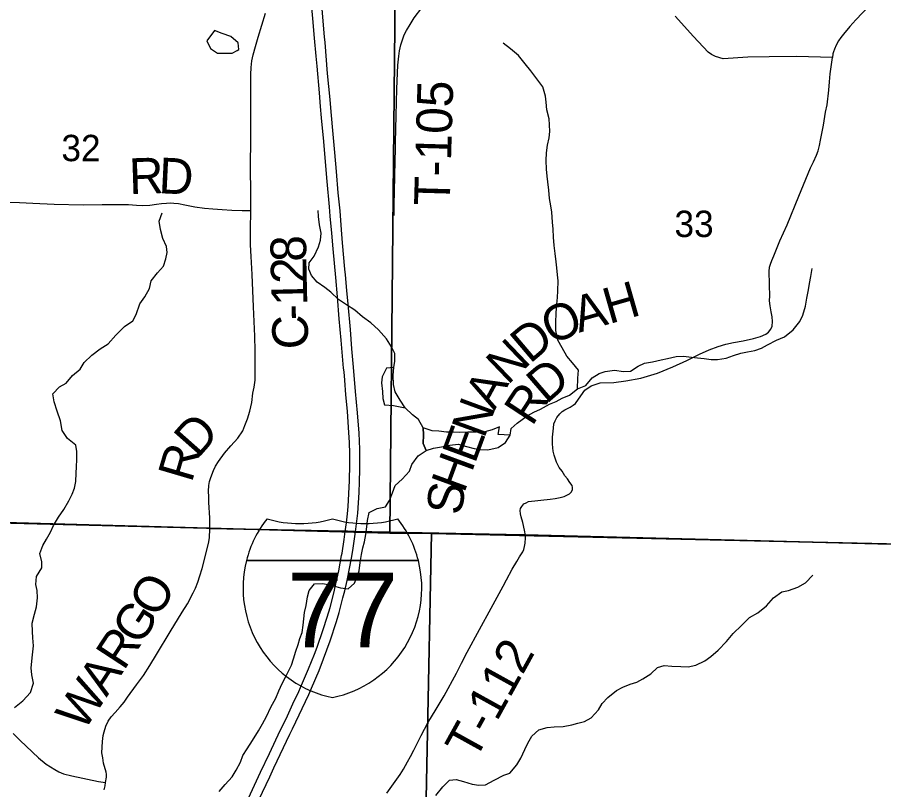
# Model space of a CAD drawing. Extents: x 0 to 34, y 0 to 22.
# Drawn here: x 6.166 to 7.543, y 15.63 to 16.857 of the extents above; entities that cross this region are included whole.
import ezdxf

# ---------------------------------------------------------------- set-up
doc = ezdxf.new("R2010")
doc.units = 0
for name, color, linetype in [('GM_X_Corporation', 7, 'Continuous'), ('GM_X_County_Road', 7, 'Continuous'), ('GM_X_County_Road_Text', 7, 'Continuous'), ('GM_X_Interstate_Location', 7, 'Continuous'), ('GM_X_Interstate_Route', 7, 'Continuous'), ('GM_X_Interstate_Shield', 7, 'Continuous'), ('GM_X_Minor_Lake', 7, 'Continuous'), ('GM_X_Minor_River', 7, 'Continuous'), ('GM_X_Section_Text', 7, 'Continuous'), ('GM_X_Township_Road', 7, 'Continuous'), ('GM_X_Township_Road_Text', 7, 'Continuous')]:
    doc.layers.add(name, color=color, linetype=linetype)

msp = doc.modelspace()

# ---------------------------------------------------------------- linework, layer by layer
at = {"layer": 'GM_X_Corporation'}
for points in [[(4.7905, 18.3604), (4.7823, 18.128), (4.7806, 18.0273), (4.765, 16.8754), (4.756, 16.2274), (4.759, 16.0879), (4.9206, 16.0842), (4.928, 16.0841), (4.9731, 16.0831), (4.975, 16.083), (5.0347, 16.0817), (5.0373, 16.0816), (6.4668, 16.045), (6.4721, 16.0449), (6.6873, 16.0404), (6.6909, 16.0403), (6.7034, 16.04), (6.9699, 16.0345), (6.9736, 16.0344), (7.8043, 16.0135), (7.8077, 16.0135), (8.4311, 16.0029), (8.4311, 20.028)], [(3.7221, 14.5734), (8.4311, 14.5734), (8.4311, 16.0029), (7.8077, 16.0135), (7.8043, 16.0135), (6.9736, 16.0344), (6.9699, 16.0345), (6.7034, 16.04), (6.6909, 16.0403), (6.6873, 16.0404), (6.4721, 16.0449), (6.4668, 16.045), (5.0373, 16.0816)]]:
    msp.add_lwpolyline(points, dxfattribs=at)
for points in [[(6.7684, 17.0582), (6.7585, 16.0372), (5.82, 16.0635), (5.7783, 16.0638), (5.7733, 17.0918)], [(7.7982, 17.0659), (7.8046, 16.0144), (6.8244, 16.0368), (6.7585, 16.0372), (6.7684, 17.0582)], [(5.82, 16.0635), (6.7585, 16.0372), (6.8244, 16.0368), (6.804, 15.0104), (5.7937, 15.0184)], [(6.8244, 16.0368), (7.8046, 16.0144), (7.7958, 14.9961), (6.804, 15.0104)]]:
    msp.add_lwpolyline(points, close=True, dxfattribs=at)
at = {"layer": 'GM_X_County_Road'}
for points in [[(7.5207, 16.8756), (7.4991, 16.8527), (7.4896, 16.8425), (7.4794, 16.8303), (7.4751, 16.8247), (7.4715, 16.8193), (7.468, 16.8128), (7.4653, 16.8065), (7.4636, 16.8022), (7.4626, 16.7986), (7.462, 16.7929), (7.4046, 16.7944), (7.3612, 16.7942), (7.3274, 16.7935), (7.2881, 16.7911), (7.2762, 16.7945), (7.2697, 16.7976), (7.2646, 16.8015), (7.2412, 16.8262), (7.2117, 16.8589)], [(6.4723, 16.0472), (6.4723, 16.0618), (6.4708, 16.0862), (6.4704, 16.0949), (6.47, 16.1041), (6.4704, 16.1128), (6.4716, 16.1192), (6.4737, 16.1259), (6.4778, 16.1367), (6.4813, 16.1438), (6.486, 16.1514), (6.4954, 16.1645), (6.5056, 16.176), (6.5169, 16.1884), (6.5244, 16.2001), (6.5279, 16.2085), (6.532, 16.2189), (6.5359, 16.2313), (6.5388, 16.245), (6.5407, 16.2595), (6.5426, 16.269), (6.544, 16.2805), (6.5443, 16.2919), (6.5444, 16.3002), (6.5442, 16.3116), (6.544, 16.3268), (6.5435, 16.3502), (6.5413, 16.3968), (6.5394, 16.448), (6.5377, 16.4771), (6.5369, 16.4954), (6.5368, 16.519), (6.5375, 16.55), (6.5375, 16.5775), (6.5366, 16.6182), (6.5368, 16.6318), (6.5373, 16.6517), (6.5374, 16.683), (6.5375, 16.7112), (6.5374, 16.7438), (6.5374, 16.7581), (6.5374, 16.7661), (6.5376, 16.7771), (6.5391, 16.7879), (6.541, 16.7973), (6.5448, 16.8104), (6.5491, 16.8253), (6.5606, 16.8635)], [(6.3042, 15.6295), (6.3057, 15.6357), (6.3064, 15.641), (6.3079, 15.6496), (6.3077, 15.6542), (6.3071, 15.6578), (6.3032, 15.6719), (6.3018, 15.6801), (6.3007, 15.6884), (6.3016, 15.7065), (6.3026, 15.7158), (6.304, 15.7218), (6.307, 15.7308), (6.3103, 15.7384), (6.3154, 15.7455), (6.3214, 15.7525), (6.3298, 15.7616), (6.3358, 15.7687), (6.3413, 15.7767), (6.3555, 15.7964), (6.3668, 15.8109), (6.377, 15.8272), (6.3872, 15.8444), (6.4091, 15.8806), (6.4284, 15.9117), (6.4365, 15.9252), (6.4457, 15.9424), (6.4491, 15.9501), (6.453, 15.9595), (6.4565, 15.9693), (6.4599, 15.9811), (6.47, 16.0207), (6.4715, 16.0298), (6.4723, 16.0443), (6.4723, 16.0472)], [(6.1595, 15.7191), (6.1705, 15.7081), (6.1803, 15.6988), (6.1998, 15.6805), (6.212, 15.6705), (6.2256, 15.6618), (6.2321, 15.6582), (6.2395, 15.655), (6.2527, 15.6517), (6.2951, 15.6427), (6.3064, 15.641)]]:
    msp.add_lwpolyline(points, dxfattribs=at)
at = {"layer": 'GM_X_Interstate_Route'}
for points in [[(6.5303, 15.6094), (6.5528, 15.6576), (6.567, 15.6873), (6.5841, 15.7238), (6.5934, 15.7425), (6.6043, 15.7661), (6.6135, 15.7857), (6.6165, 15.7923), (6.6291, 15.8215), (6.6384, 15.8449), (6.6429, 15.8564), (6.6525, 15.8844), (6.6587, 15.904), (6.6632, 15.9191), (6.6701, 15.9463), (6.6709, 15.9499), (6.6772, 15.9777), (6.6817, 16.0019), (6.6824, 16.0056), (6.6858, 16.0273), (6.6875, 16.0398), (6.6893, 16.0536), (6.6908, 16.0678), (6.6919, 16.0798), (6.6944, 16.1205), (6.6947, 16.1462), (6.6945, 16.1641), (6.6941, 16.1816), (6.6928, 16.205), (6.6909, 16.2313), (6.6885, 16.2572), (6.6865, 16.2803), (6.6855, 16.2935), (6.6849, 16.2996), (6.6809, 16.3438), (6.6796, 16.3609), (6.678, 16.3779), (6.6749, 16.4126), (6.6723, 16.4434), (6.6682, 16.4891), (6.6661, 16.5138), (6.6636, 16.5409), (6.6623, 16.556), (6.6588, 16.5958), (6.6561, 16.6272), (6.6533, 16.6598), (6.6497, 16.6974), (6.6481, 16.7151), (6.6463, 16.737), (6.6426, 16.7794), (6.6414, 16.7949), (6.6387, 16.8239), (6.6359, 16.8552), (6.634, 16.8779)], [(6.5385, 15.5891), (6.5676, 15.6502), (6.574, 15.6644), (6.5995, 15.7179), (6.6035, 15.7263), (6.6294, 15.7811), (6.634, 15.7912), (6.6458, 15.8193), (6.6531, 15.8376), (6.6636, 15.8661), (6.6734, 15.897), (6.6775, 15.9115), (6.6838, 15.9344), (6.6865, 15.9459), (6.6902, 15.9623), (6.6942, 15.9813), (6.6972, 15.9974), (6.6994, 16.0099), (6.7036, 16.0395), (6.7072, 16.0691), (6.7094, 16.1018), (6.71, 16.1186), (6.7106, 16.1386), (6.7105, 16.171), (6.7095, 16.196), (6.7071, 16.2285), (6.7039, 16.2626), (6.7006, 16.3012), (6.6981, 16.3303), (6.6956, 16.3607), (6.6918, 16.4012), (6.69, 16.4229), (6.6878, 16.4476), (6.6869, 16.4569), (6.6833, 16.4987), (6.6814, 16.5193), (6.6791, 16.5494), (6.6764, 16.578), (6.6734, 16.6121), (6.6707, 16.6422), (6.6671, 16.6827), (6.6644, 16.7133), (6.6632, 16.7261), (6.6594, 16.7677), (6.6553, 16.8166), (6.6544, 16.826), (6.6501, 16.8761)]]:
    msp.add_lwpolyline(points, dxfattribs=at)
at = {"layer": 'GM_X_Interstate_Shield'}
for p, q in [((6.5304, 15.9937), (6.8036, 15.9937)), ((6.8036, 15.9937), (6.5304, 15.9937)), ((6.8036, 15.9937), (6.5304, 15.9937))]:
    msp.add_line(p, q, dxfattribs=at)
for centre, start, end in [((6.7025, 15.9501), 141.669, 165.8066), ((6.6151, 16.2301), 253.0091, 286.9909), ((6.7189, 16.2301), 253.0091, 286.9909), ((6.6315, 15.9501), 14.1934, 38.331), ((6.7025, 15.9501), 165.8066, 258.463), ((6.6315, 15.9501), 281.537, 14.1934)]:
    msp.add_arc(centre, 0.1776, start, end, dxfattribs=at)
at = {"layer": 'GM_X_Minor_Lake'}
for points in [[(6.4793, 16.8357), (6.4673, 16.8197), (6.4734, 16.8072), (6.4844, 16.8), (6.5075, 16.8001), (6.5156, 16.8044)], [(6.5156, 16.8044), (6.5184, 16.8058), (6.5172, 16.8165), (6.5055, 16.8263), (6.4918, 16.8311), (6.4793, 16.8357)], [(6.7645, 16.3006), (6.7532, 16.2994), (6.746, 16.2858), (6.7449, 16.2763), (6.7464, 16.2623), (6.7472, 16.2513), (6.7499, 16.2411), (6.7639, 16.2403), (6.7829, 16.2366)], [(6.7829, 16.2366), (6.7745, 16.2487), (6.7669, 16.262), (6.7642, 16.2733), (6.7634, 16.2885), (6.7645, 16.3006)], [(6.8114, 16.2045), (6.8118, 16.1935), (6.8111, 16.1799), (6.816, 16.1685), (6.8277, 16.1723), (6.8406, 16.1747), (6.8539, 16.177), (6.8667, 16.1785), (6.88, 16.1752), (6.8921, 16.1718), (6.9016, 16.1703), (6.9141, 16.1696), (6.9307, 16.1735), (6.9421, 16.1811), (6.9496, 16.1932)], [(6.9496, 16.1932), (6.9307, 16.1939), (6.9329, 16.2061), (6.9208, 16.2015), (6.9091, 16.1984), (6.8958, 16.198), (6.8822, 16.1979), (6.8697, 16.1971), (6.8595, 16.1978), (6.8485, 16.1978), (6.8364, 16.1993), (6.8254, 16.2), (6.8114, 16.2045)]]:
    msp.add_lwpolyline(points, dxfattribs=at)
at = {"layer": 'GM_X_Minor_River'}
for points in [[(7.0565, 16.2668), (7.0572, 16.2838), (7.058, 16.296), (7.0485, 16.3081), (7.0397, 16.3186), (7.0321, 16.3319), (7.0256, 16.344), (7.0222, 16.3595), (7.0221, 16.3713), (7.0229, 16.3876), (7.0236, 16.4009), (7.0247, 16.4119), (7.0254, 16.4225), (7.0257, 16.438), (7.0249, 16.4479), (7.0238, 16.4589), (7.0226, 16.4683), (7.0211, 16.4816), (7.0195, 16.4941), (7.0183, 16.5074), (7.0179, 16.5202), (7.0167, 16.5312), (7.0156, 16.5475), (7.014, 16.5574), (7.0121, 16.5691), (7.0109, 16.582), (7.0097, 16.5953), (7.0086, 16.6047), (7.0074, 16.6154), (7.0066, 16.6294), (7.0073, 16.6415), (7.0092, 16.654), (7.0114, 16.6654), (7.0125, 16.6753), (7.0121, 16.6863), (7.0117, 16.6957), (7.0079, 16.7101), (7.0067, 16.7223), (7.0059, 16.7317), (7.0017, 16.7465), (6.9918, 16.759), (6.9827, 16.7718), (6.9736, 16.7832), (6.963, 16.796), (6.95, 16.8066), (6.9383, 16.816)], [(6.1618, 15.7601), (6.1747, 15.7708), (6.1871, 15.7841), (6.192, 15.7989), (6.1889, 15.8122), (6.1882, 15.8236), (6.1904, 15.844), (6.1918, 15.8581), (6.1907, 15.871), (6.1903, 15.8812), (6.1898, 15.8945), (6.1932, 15.9085), (6.1966, 15.9203), (6.198, 15.9343), (6.1976, 15.946), (6.1953, 15.9555), (6.1968, 15.9684), (6.2051, 15.9821), (6.2051, 15.9916), (6.202, 16.0052), (6.2069, 16.0177), (6.2125, 16.0276), (6.2189, 16.039), (6.2234, 16.0493), (6.2317, 16.0626), (6.24, 16.0751), (6.2479, 16.0884), (6.2532, 16.0994), (6.257, 16.1089), (6.2592, 16.1195), (6.2599, 16.1324), (6.2603, 16.1427), (6.2606, 16.1544), (6.2606, 16.1673), (6.259, 16.1771), (6.2457, 16.1877), (6.2374, 16.2006), (6.2347, 16.2157), (6.2297, 16.2313), (6.2248, 16.246), (6.2224, 16.2589), (6.2334, 16.2696), (6.244, 16.2757), (6.2538, 16.2878), (6.2659, 16.2977), (6.2723, 16.3084), (6.2844, 16.3202), (6.2976, 16.3301), (6.3104, 16.3381), (6.3225, 16.3521), (6.3365, 16.3655), (6.3497, 16.3746), (6.355, 16.3849), (6.361, 16.4016), (6.3689, 16.413), (6.3764, 16.4259), (6.379, 16.4384), (6.3892, 16.4509), (6.3983, 16.4616), (6.402, 16.473), (6.4043, 16.4832), (6.4035, 16.4927), (6.3974, 16.5052), (6.3939, 16.5196), (6.3916, 16.5332), (6.3965, 16.5461)], [(6.816, 16.1685), (6.8111, 16.1799), (6.8118, 16.1935), (6.8114, 16.2045), (6.8038, 16.2181), (6.7943, 16.2253), (6.7829, 16.2366), (6.7745, 16.2487), (6.7669, 16.262), (6.7642, 16.2733), (6.7634, 16.2885), (6.7645, 16.3006), (6.7664, 16.3105), (6.766, 16.323), (6.761, 16.3332), (6.753, 16.3461), (6.7405, 16.3601), (6.728, 16.3714), (6.715, 16.3808), (6.7029, 16.3914), (6.6892, 16.4001), (6.6767, 16.4087), (6.6646, 16.4201), (6.6547, 16.4276), (6.6426, 16.4359), (6.6338, 16.4465), (6.6296, 16.4567), (6.63, 16.4666), (6.6379, 16.4776), (6.6451, 16.492), (6.648, 16.5027), (6.6491, 16.514), (6.6465, 16.5273), (6.6449, 16.5402), (6.6445, 16.55)], [(7.3271, 16.3253), (7.3388, 16.3276), (7.349, 16.3311), (7.3589, 16.3364), (7.3728, 16.3441), (7.3857, 16.3494), (7.3997, 16.3605), (7.4102, 16.3734), (7.4151, 16.3836), (7.4192, 16.3981), (7.4211, 16.4106), (7.4237, 16.4238), (7.4256, 16.4341), (7.4274, 16.4451), (7.4297, 16.4576)], [(6.4871, 15.6271), (6.4965, 15.6381), (6.5075, 15.6499), (6.5139, 15.6609), (6.5207, 15.6735), (6.5248, 15.6841), (6.5316, 15.6947), (6.5402, 15.708), (6.5497, 15.7232), (6.5561, 15.7346), (6.5621, 15.746), (6.5689, 15.7608), (6.5768, 15.7753), (6.582, 15.787), (6.5873, 15.7984), (6.5922, 15.8087), (6.602, 15.8277), (6.605, 15.8375), (6.6091, 15.8497), (6.6125, 15.8603), (6.6151, 15.8698), (6.6189, 15.8797), (6.6203, 15.8911), (6.6218, 15.9013), (6.6229, 15.9112), (6.6255, 15.9225), (6.6274, 15.9362), (6.63, 15.9464), (6.6387, 15.9567), (6.6516, 15.9575), (6.6648, 15.9545), (6.68, 15.9504), (6.6921, 15.9486), (6.7023, 15.9581), (6.7057, 15.9676), (6.7094, 15.9774), (6.7113, 15.9907), (6.7135, 16.0032), (6.7154, 16.0138), (6.718, 16.0237), (6.7202, 16.0351), (6.7217, 16.0476), (6.7228, 16.0575), (6.7254, 16.07), (6.7379, 16.0765), (6.7515, 16.0792), (6.7579, 16.0891), (6.7625, 16.1012), (6.7666, 16.113), (6.7779, 16.1233), (6.7896, 16.1358), (6.7934, 16.1464), (6.8035, 16.1601), (6.816, 16.1685), (6.8277, 16.1723), (6.8406, 16.1747), (6.8539, 16.177), (6.8667, 16.1785), (6.88, 16.1752), (6.8921, 16.1718), (6.9016, 16.1703), (6.9141, 16.1696), (6.9307, 16.1735), (6.9421, 16.1811), (6.9496, 16.1932), (6.9511, 16.2035), (6.9609, 16.2118), (6.9764, 16.2237), (6.987, 16.2294), (6.9976, 16.2343), (7.0119, 16.242), (7.0225, 16.2466), (7.0323, 16.2519), (7.0437, 16.2565), (7.0565, 16.2668), (7.0701, 16.2721), (7.08, 16.2843), (7.0909, 16.2912), (7.1007, 16.2942), (7.1155, 16.2965), (7.1299, 16.2943), (7.1409, 16.2947), (7.153, 16.3027), (7.1632, 16.3073), (7.1761, 16.3096), (7.1897, 16.3127), (7.1999, 16.315), (7.2135, 16.3181), (7.2249, 16.3185), (7.2377, 16.3171), (7.2476, 16.316), (7.2582, 16.3149), (7.2692, 16.3134), (7.2794, 16.3134), (7.293, 16.3154), (7.3048, 16.3196), (7.3161, 16.3234), (7.3271, 16.3253)], [(6.8313, 15.6203), (6.8426, 15.6344), (6.8532, 15.6447), (6.8638, 15.6459), (6.8755, 15.6429), (6.8892, 15.6387), (6.8998, 15.6369), (6.9104, 15.6373), (6.9244, 15.6446), (6.9395, 15.6526), (6.9493, 15.656), (6.9603, 15.6693), (6.9667, 15.68), (6.9731, 15.6936), (6.9776, 15.7039), (6.984, 15.7149), (6.9953, 15.7248), (7.0082, 15.7283), (7.0195, 15.7294), (7.0339, 15.7302), (7.0475, 15.733), (7.0574, 15.7353), (7.0676, 15.7383), (7.0785, 15.7441), (7.0899, 15.7566), (7.0959, 15.7665), (7.1046, 15.7764), (7.1189, 15.7874), (7.1288, 15.7928), (7.1401, 15.7973), (7.1507, 15.8008), (7.1605, 15.8058), (7.1734, 15.8138), (7.1836, 15.8237), (7.1942, 15.8271), (7.2066, 15.826), (7.2207, 15.8253), (7.2324, 15.825), (7.2449, 15.8277), (7.2589, 15.8342), (7.2687, 15.8414), (7.28, 15.8513), (7.2936, 15.865), (7.3042, 15.8779), (7.3174, 15.8905), (7.3299, 15.9034), (7.3431, 15.9107), (7.3571, 15.9221), (7.3684, 15.9346), (7.3816, 15.9442), (7.3922, 15.9461), (7.4069, 15.9514), (7.419, 15.9583), (7.4307, 15.9705)]]:
    msp.add_lwpolyline(points, dxfattribs=at)
at = {"layer": 'GM_X_Township_Road'}
for points in [[(6.7674, 16.6578), (6.7683, 16.7007), (6.7692, 16.7431), (6.7712, 16.7806), (6.7724, 16.7951), (6.7738, 16.8038), (6.7756, 16.8129), (6.7812, 16.829), (6.7847, 16.8357), (6.7905, 16.8457), (6.7969, 16.8562), (6.8092, 16.8717), (6.8239, 16.8876), (6.8325, 16.8974)], [(6.9737, 16.0242), (6.9739, 16.0271), (6.9738, 16.0338), (6.9724, 16.0422), (6.9698, 16.054), (6.9669, 16.0634), (6.9658, 16.068), (6.9656, 16.0735), (6.9661, 16.0764), (6.9679, 16.0798), (6.9715, 16.0837), (6.9748, 16.0856), (6.9789, 16.0874), (7.0132, 16.0912), (7.0209, 16.0925), (7.029, 16.0941), (7.0352, 16.0958), (7.0399, 16.0975), (7.0441, 16.0996), (7.0465, 16.1024), (7.0486, 16.1063), (7.0486, 16.1096), (7.0479, 16.113), (7.0447, 16.118), (7.0406, 16.1236), (7.0364, 16.1283), (7.0321, 16.1356), (7.0277, 16.1415), (7.0233, 16.1502), (7.0194, 16.1611), (7.018, 16.1678), (7.0175, 16.1728), (7.0168, 16.1794), (7.0167, 16.1843), (7.0167, 16.1898), (7.0183, 16.2041), (7.0192, 16.2108), (7.0213, 16.216), (7.0239, 16.2212), (7.0284, 16.2271), (7.0321, 16.2307), (7.0364, 16.2334), (7.0452, 16.2373), (7.0495, 16.2405), (7.0533, 16.2433), (7.062, 16.2553), (7.0682, 16.2643), (7.0786, 16.2714), (7.0929, 16.276), (7.1142, 16.2769), (7.1335, 16.2793), (7.1571, 16.2836), (7.1836, 16.2915), (7.2081, 16.3014), (7.2303, 16.3116), (7.2504, 16.3219), (7.2659, 16.3286), (7.2803, 16.3337), (7.2925, 16.3376), (7.3047, 16.3403), (7.3198, 16.3431), (7.3364, 16.3466), (7.3477, 16.3495), (7.3559, 16.3535), (7.3602, 16.3569), (7.3638, 16.3614), (7.3661, 16.3663), (7.3668, 16.3735), (7.3659, 16.3812), (7.3646, 16.3888), (7.3628, 16.3987), (7.3621, 16.4064), (7.3623, 16.4143), (7.3617, 16.4313), (7.3621, 16.4394), (7.3614, 16.4468), (7.3614, 16.4529), (7.3621, 16.4598), (7.3633, 16.4649), (7.3655, 16.4707), (7.3686, 16.4779), (7.3785, 16.502), (7.3897, 16.5271), (7.4086, 16.5725), (7.4273, 16.6176), (7.4318, 16.6271), (7.4368, 16.6381), (7.4393, 16.6446), (7.4416, 16.6531), (7.4428, 16.6619), (7.4477, 16.6853), (7.451, 16.7062), (7.4536, 16.718), (7.4564, 16.7411), (7.457, 16.7542), (7.4582, 16.7673), (7.462, 16.7929)], [(6.7653, 16.5421), (6.7651, 16.5515), (6.7653, 16.5606), (6.7656, 16.5788), (6.7664, 16.606), (6.7672, 16.649), (6.7674, 16.6578)], [(6.139, 16.5636), (6.1696, 16.5624), (6.1909, 16.5616), (6.2249, 16.56), (6.271, 16.5592), (6.3011, 16.5595), (6.3195, 16.5593), (6.3428, 16.5594), (6.3556, 16.5584), (6.3644, 16.5579), (6.3767, 16.5584), (6.3874, 16.5599), (6.3952, 16.5612), (6.403, 16.5618), (6.409, 16.5619), (6.4149, 16.5617), (6.4223, 16.5608), (6.4323, 16.5591), (6.4482, 16.5558), (6.4637, 16.5537), (6.477, 16.5525), (6.4917, 16.5513), (6.5069, 16.5503), (6.5236, 16.5499), (6.5375, 16.55)], [(6.7534, 15.6242), (6.7745, 15.6537), (6.7801, 15.6625), (6.7866, 15.6739), (6.7912, 15.6823), (6.7966, 15.6927), (6.808, 15.7158), (6.8188, 15.7362), (6.8319, 15.7579), (6.8445, 15.7787), (6.8641, 15.8147), (6.8721, 15.831), (6.8813, 15.8482), (6.9009, 15.8843), (6.9195, 15.918), (6.9384, 15.9533), (6.9438, 15.9634), (6.9527, 15.98), (6.9602, 15.9924), (6.9646, 15.9995), (6.9695, 16.0075), (6.9713, 16.0113), (6.9726, 16.0161), (6.9735, 16.0212), (6.9737, 16.0242)]]:
    msp.add_lwpolyline(points, dxfattribs=at)

# ---------------------------------------------------------------- texts
at = {"layer": 'GM_X_County_Road_Text'}
for s, rotation, p in [('8', 90.9866, (6.6257, 16.4689)), ('2', 91.2111, (6.6264, 16.4342)), ('1', 91.3298, (6.6272, 16.3995)), ('-', 91.4141, (6.6278, 16.3764)), ('C', 91.4422, (6.6289, 16.3301)), ('D', 48.5156, (6.4533, 16.1552)), ('R', 73.5748, (6.4433, 16.1162)), ('O', 59.3741, (6.3896, 15.9009)), ('G', 56.9469, (6.3609, 15.8568)), ('R', 56.8652, (6.3354, 15.8176)), ('A', 56.7204, (6.3078, 15.7757)), ('W', 56.5977, (6.2715, 15.7206))]:
    msp.add_text(s, height=0.0568, rotation=rotation, dxfattribs=at).set_placement(p)
at = {"layer": 'GM_X_Interstate_Location'}
for s in ['-', '.', ',']:
    msp.add_text(s, height=0.000189, dxfattribs=at).set_placement((6.667, 15.9181))
msp.add_text('77', height=0.000189, rotation=0, dxfattribs=at).set_placement((6.6283, 15.8789))
at = {"layer": 'GM_X_Interstate_Shield'}
msp.add_text('77', height=0.11837, dxfattribs=at).set_placement((6.5951, 15.8561))
at = {"layer": 'GM_X_Section_Text'}
for s, p in [('32', (6.2362, 16.6283)), ('33', (7.2108, 16.5078))]:
    msp.add_text(s, height=0.04186, rotation=0, dxfattribs=at).set_placement(p)
at = {"layer": 'GM_X_Township_Road_Text'}
for s, height, rotation, p in [('T-105', 0.05682, 88.3577, (6.8535, 16.5571)), ('R', 0.0568, 1.8465, (6.3446, 16.5759)), ('D', 0.0568, 357.256, (6.39, 16.5775)), ('H', 0.0568, 15.9459, (7.107, 16.3693)), ('A', 0.0568, 16.0209, (7.059, 16.3556)), ('O', 0.0568, 24.5217, (7.0156, 16.3356)), ('D', 0.0568, 40.3508, (6.981, 16.3054)), ('N', 0.0568, 43.7558, (6.9455, 16.2714)), ('D', 0.0568, 40.87, (7.0071, 16.2416)), ('A', 0.0568, 61.6704, (6.9246, 16.2311)), ('R', 0.0568, 56.7819, (6.9843, 16.2057)), ('N', 0.0568, 69.762, (6.9082, 16.1862)), ('E', 0.0568, 69.7745, (6.8935, 16.1463)), ('H', 0.0568, 69.8933, (6.8763, 16.0994)), ('S', 0.0568, 83.017, (6.8725, 16.0647)), ('T-112', 0.05682, 61.0546, (6.8937, 15.6742))]:
    msp.add_text(s, height=height, rotation=rotation, dxfattribs=at).set_placement(p)

doc.saveas('drawing.dxf')
